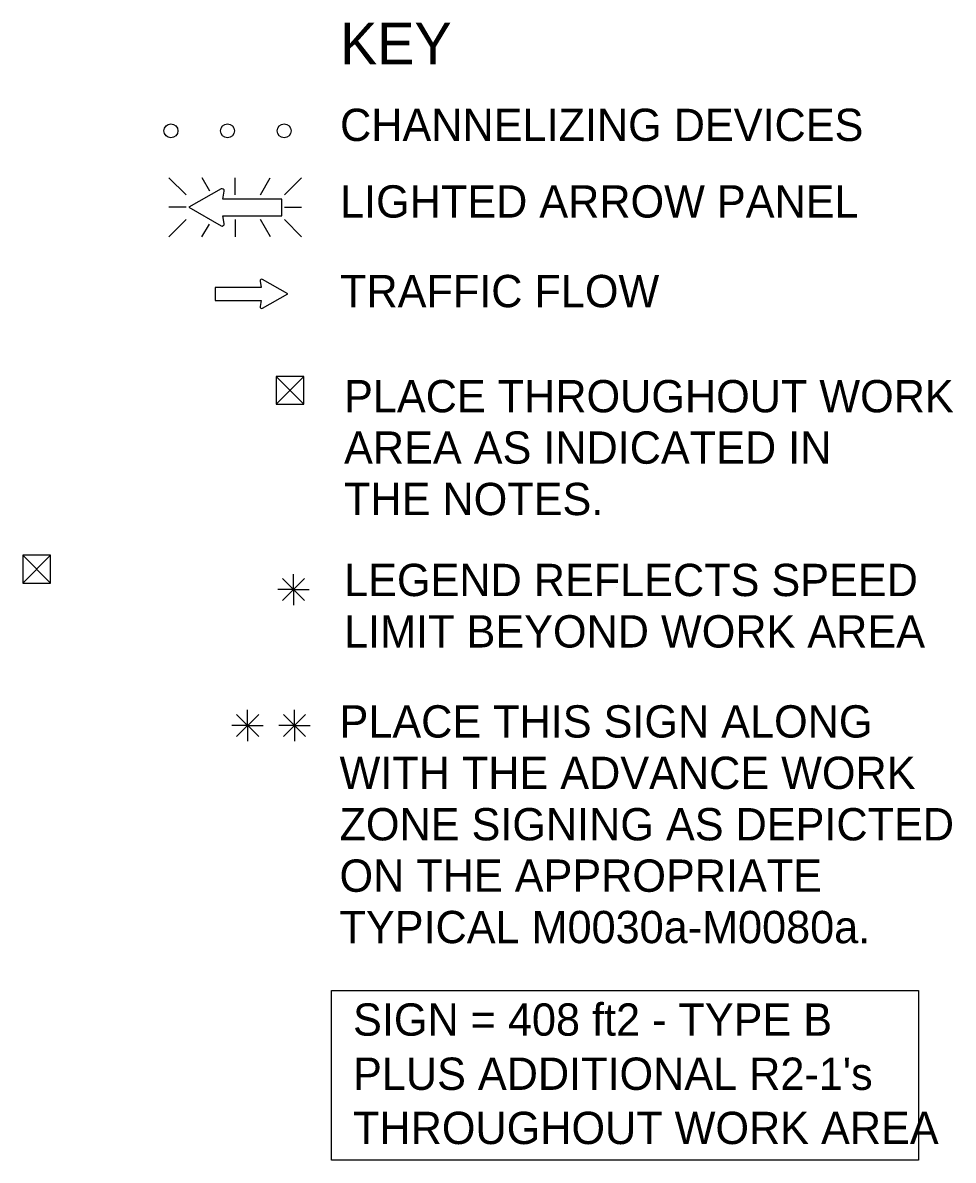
# Model space of a CAD drawing. Extents: x 16725 to 18479, y 5932 to 7023.
# Drawn here: x 17141 to 17408.9, y 6584.9 to 6912.4 of the extents above; entities that cross this region are included whole.
import ezdxf

# ---------------------------------------------------------------- set-up
doc = ezdxf.new("R2010")
doc.units = 0
for name, color, linetype in [('MT_SCRATCH_LEVEL_E', 7, 'Continuous'), ('TRAFFIC_SIGNS_PR', 7, 'Continuous'), ('TYPICAL_TEXT_DIMEN_EX', 7, 'Continuous'), ('TYPICAL_TEXT_DIMEN_PR', 7, 'Continuous')]:
    doc.layers.add(name, color=color, linetype=linetype)

msp = doc.modelspace()

# ---------------------------------------------------------------- linework, layer by layer
at = {"layer": 'MT_SCRATCH_LEVEL_E'}
for p, q in [((17209.35, 6837.96), (17209.66, 6836.18)), ((17217.27, 6834.33), (17210.03, 6838.44)), ((17209.66, 6836.18), (17196.4, 6836.18)), ((17196.4, 6836.18), (17196.4, 6832.44)), ((17196.4, 6832.44), (17209.66, 6832.44)), ((17209.66, 6832.44), (17209.35, 6830.66)), ((17210.03, 6830.19), (17217.27, 6834.33))]:
    msp.add_line(p, q, dxfattribs=at)
for centre, start, end in [((17209.81, 6838.04), 60.4248, 189.9638), ((17209.81, 6830.59), 170.0362, 299.7731)]:
    msp.add_arc(centre, 0.463, start, end, dxfattribs=at)
at = {"layer": 'TRAFFIC_SIGNS_PR'}
for p, q in [((17183.08, 6867.71), (17188.02, 6862.78)), ((17194.85, 6863.89), (17192.64, 6867.72)), ((17202.17, 6862.78), (17202.17, 6867.72)), ((17209.4, 6862.78), (17212.25, 6867.72)), ((17216.31, 6862.78), (17221.25, 6867.72)), ((17188.02, 6859.23), (17183.08, 6859.23)), ((17216.31, 6859.23), (17221.25, 6859.23)), ((17183.08, 6850.74), (17188.02, 6855.67)), ((17192.59, 6850.74), (17194.71, 6854.4)), ((17202.17, 6855.67), (17202.17, 6850.74)), ((17212.29, 6850.74), (17209.44, 6855.67)), ((17216.31, 6855.67), (17221.25, 6850.73))]:
    msp.add_line(p, q, dxfattribs=at)
for points in [[(17198.09, 6864.5), (17188.8, 6859.23), (17198.1, 6853.9)], [(17198.97, 6854.53), (17198.57, 6856.8), (17215.58, 6856.8), (17215.58, 6861.6), (17198.57, 6861.6), (17198.97, 6863.88)]]:
    msp.add_lwpolyline(points, dxfattribs=at)
for centre in [(17183.65, 6881.26), (17199.95, 6881.26), (17216.25, 6881.26)]:
    msp.add_circle(centre, 2, dxfattribs=at)
for centre, radius, start, end in [((17198.38, 6863.98), 0.598, 350.7308, 118.8916), ((17198.38, 6854.43), 0.597, 241.4833, 9.9593)]:
    msp.add_arc(centre, radius, start, end, dxfattribs=at)
at = {"layer": 'TYPICAL_TEXT_DIMEN_EX'}
msp.add_lwpolyline([(17229.85, 6633.7), (17398.86, 6633.7), (17398.86, 6584.87), (17229.85, 6584.87)], close=True, dxfattribs=at)
at = {"layer": 'TYPICAL_TEXT_DIMEN_PR'}
for p, q in [((17213.9, 6802.55), (17221.9, 6810.55)), ((17213.91, 6810.55), (17221.9, 6802.55)), ((17140.99, 6759.03), (17148.99, 6751.03)), ((17140.99, 6751.03), (17148.99, 6759.03)), ((17218.95, 6749.19), (17218.95, 6753.64)), ((17215.76, 6752.37), (17222.14, 6746)), ((17222.14, 6752.37), (17215.76, 6746)), ((17218.95, 6749.19), (17214.42, 6749.19)), ((17218.95, 6749.19), (17222.14, 6749.19)), ((17218.95, 6749.19), (17223.43, 6749.19)), ((17218.95, 6749.19), (17218.95, 6744.69)), ((17205.73, 6710.06), (17205.73, 6714.51)), ((17219.23, 6710.06), (17219.23, 6714.51)), ((17202.54, 6713.24), (17208.92, 6706.87)), ((17208.92, 6713.24), (17202.54, 6706.87)), ((17216.05, 6713.24), (17222.42, 6706.87)), ((17222.42, 6713.24), (17216.05, 6706.87)), ((17205.73, 6710.06), (17201.2, 6710.06)), ((17205.73, 6710.06), (17208.92, 6710.06)), ((17205.73, 6710.06), (17210.21, 6710.06)), ((17205.73, 6710.06), (17205.73, 6705.56)), ((17219.23, 6710.06), (17214.7, 6710.06)), ((17219.23, 6710.06), (17222.42, 6710.06)), ((17219.23, 6710.06), (17223.71, 6710.06)), ((17219.23, 6710.06), (17219.23, 6705.56))]:
    msp.add_line(p, q, dxfattribs=at)
for points in [[(17213.91, 6810.55), (17213.9, 6802.55), (17221.9, 6802.55), (17221.9, 6810.55)], [(17140.99, 6759.03), (17140.99, 6751.03), (17148.99, 6751.03), (17148.99, 6759.03)]]:
    msp.add_lwpolyline(points, close=True, dxfattribs=at)
msp.add_open_spline([(17311.9, 6749.77), (17311.92, 6749.77), (17311.93, 6749.77), (17311.93, 6749.77)], degree=2, dxfattribs=at)

# ---------------------------------------------------------------- texts
at = {"layer": 'TYPICAL_TEXT_DIMEN_EX'}
for s, height, p in [('KEY', 12, (17232.34, 6900.36)), ('CHANNELIZING DEVICES', 9.3, (17232.34, 6878.31)), ('LIGHTED ARROW PANEL', 9.3, (17232.34, 6856.26)), ('TRAFFIC FLOW', 9.3, (17232.34, 6830.46)), ('PLACE THROUGHOUT WORK', 9.3, (17233.49, 6800.2)), ('AREA AS INDICATED IN', 9.3, (17233.49, 6785.4)), ('THE NOTES.', 9.3, (17233.49, 6770.6)), ('LEGEND REFLECTS SPEED', 9.3, (17233.5, 6747.29)), ('LIMIT BEYOND WORK AREA', 9.3, (17233.5, 6732.49)), ('PLACE THIS SIGN ALONG', 9.3, (17232.18, 6706.56)), ('WITH THE ADVANCE WORK', 9.3, (17232.18, 6691.76)), ('ZONE SIGNING AS DEPICTED', 9.3, (17232.18, 6676.96)), ('ON THE APPROPRIATE', 9.3, (17232.18, 6662.16)), ('TYPICAL M0030a-M0080a.', 9.3, (17232.18, 6647.36)), ('SIGN = 408 ft2 - TYPE B', 9.3, (17236.08, 6620.73)), ("PLUS ADDITIONAL R2-1's", 9.3, (17236.08, 6605.13)), ('THROUGHOUT WORK AREA', 9.3, (17236.08, 6589.53))]:
    msp.add_text(s, height=height, dxfattribs=at).set_placement(p)

doc.saveas('drawing.dxf')
